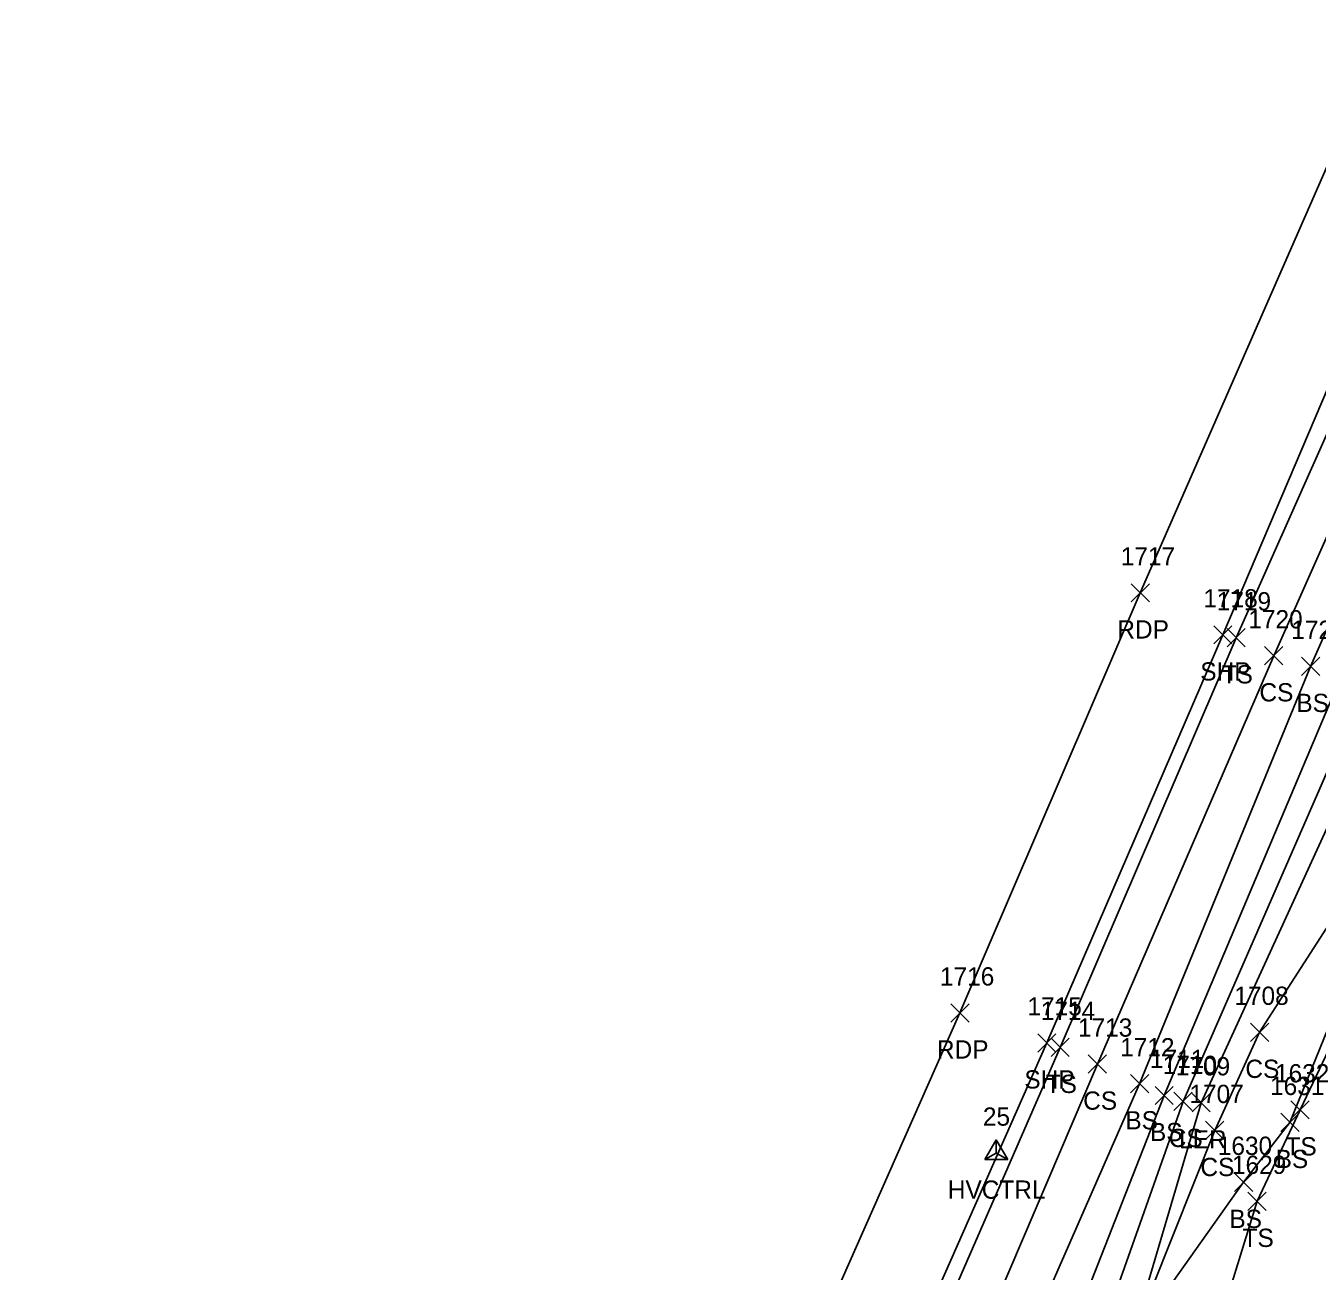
# Model space of a CAD drawing. Extents: x 1483143 to 1488182, y 802902 to 807581.
# Drawn here: x 1487613.3 to 1487754.7, y 806116.2 to 806252.6 of the extents above; entities that cross this region are included whole.
import ezdxf

# ---------------------------------------------------------------- set-up
doc = ezdxf.new("R2010")
doc.units = 0
for name, color, linetype in [('C_A', 7, 'Continuous'), ('C_I', 7, 'Continuous'), ('CPSM', 7, 'Continuous'), ('L_A', 7, 'Continuous'), ('L_I', 7, 'Continuous'), ('L_TIC', 7, 'Continuous'), ('LARO', 7, 'Continuous'), ('LELB', 7, 'Continuous'), ('P_A', 7, 'Continuous'), ('P_I', 7, 'Continuous'), ('P_TIC', 7, 'Continuous'), ('PET', 7, 'Continuous'), ('PSP', 7, 'Continuous')]:
    doc.layers.add(name, color=color, linetype=linetype)

msp = doc.modelspace()

# ---------------------------------------------------------------- linework, layer by layer
at = {"layer": 'CPSM'}
for p, q in [((1487718.34, 806128.4), (1487719.59, 806130.56)), ((1487720.84, 806128.4), (1487719.59, 806130.56)), ((1487719.59, 806129.12), (1487719.59, 806130.56)), ((1487718.34, 806128.4), (1487719.59, 806129.12)), ((1487718.34, 806128.4), (1487720.84, 806128.4)), ((1487719.59, 806129.12), (1487719.59, 806129.12)), ((1487719.59, 806129.12), (1487720.84, 806128.4))]:
    msp.add_line(p, q, dxfattribs=at)
at = {"layer": 'L_TIC'}
for points in [[(1487744.85, 806184.55), (1487746.85, 806186.55)], [(1487746.85, 806184.55), (1487744.85, 806186.55)], [(1487748.96, 806182.58), (1487750.96, 806184.58)], [(1487750.96, 806182.58), (1487748.96, 806184.58)], [(1487753, 806181.42), (1487755, 806183.42)], [(1487755, 806181.42), (1487753, 806183.42)], [(1487747.42, 806141.35), (1487749.42, 806143.35)], [(1487749.42, 806141.35), (1487747.42, 806143.35)], [(1487725.58, 806139.7), (1487727.58, 806141.7)], [(1487727.58, 806139.7), (1487725.58, 806141.7)], [(1487729.65, 806137.87), (1487731.65, 806139.87)], [(1487731.65, 806137.87), (1487729.65, 806139.87)], [(1487734.28, 806135.71), (1487736.28, 806137.71)], [(1487736.28, 806135.71), (1487734.28, 806137.71)], [(1487736.97, 806134.43), (1487738.97, 806136.43)], [(1487738.97, 806134.43), (1487736.97, 806136.43)], [(1487739.03, 806133.78), (1487741.03, 806135.78)], [(1487741.03, 806133.78), (1487739.03, 806135.78)], [(1487741.02, 806133.63), (1487743.02, 806135.63)], [(1487743.02, 806133.63), (1487741.02, 806135.63)], [(1487751.84, 806132.86), (1487753.84, 806134.86)], [(1487753.84, 806132.86), (1487751.84, 806134.86)], [(1487742.5, 806130.6), (1487744.5, 806132.6)], [(1487744.5, 806130.6), (1487742.5, 806132.6)], [(1487750.73, 806131.48), (1487752.73, 806133.48)], [(1487752.73, 806131.48), (1487750.73, 806133.48)], [(1487745.67, 806124.92), (1487747.67, 806126.92)], [(1487747.67, 806124.92), (1487745.67, 806126.92)], [(1487747.14, 806122.84), (1487749.14, 806124.84)], [(1487749.14, 806122.84), (1487747.14, 806124.84)]]:
    msp.add_lwpolyline(points, dxfattribs=at)
at = {"layer": 'LARO'}
msp.add_lwpolyline([(1487666.95, 805964.97), (1487680.31, 805984.75), (1487702.99, 806037.2), (1487715.7, 806058.03), (1487734.3, 806108.53), (1487742.02, 806134.63), (1487761.66, 806177.53), (1487786.65, 806227.9), (1487808.03, 806277.33), (1487813.76, 806294.17), (1487828.9, 806329), (1487831.91, 806346.68), (1487843.29, 806372.21), (1487845.69, 806380.48), (1487852.63, 806386.9), (1487863.18, 806416.3)], dxfattribs=at)
at = {"layer": 'LELB'}
for points in [[(1487406.66, 805485.41), (1487431.45, 805531.24), (1487454.84, 805575.74), (1487473.75, 805612.05), (1487489.43, 805642.37), (1487507.64, 805678.53), (1487524.82, 805711.39), (1487541.86, 805746.09), (1487557.67, 805776.44), (1487575.49, 805812.01), (1487597.52, 805857.93), (1487620.62, 805906.82), (1487641.85, 805951.94), (1487662.18, 805996.35), (1487684.09, 806043.93), (1487694.42, 806066.95), (1487726.58, 806140.7), (1487745.85, 806185.55), (1487769.04, 806237.65), (1487788.58, 806284.85), (1487808.3, 806333.26), (1487827.52, 806379.6), (1487850.09, 806437.73)], [(1487410.04, 805483.24), (1487436.07, 805529.53), (1487459.78, 805575.03), (1487477.42, 805609.67), (1487492.45, 805639.09), (1487509.86, 805677.27), (1487528.68, 805708.85), (1487545.3, 805744.17), (1487561.79, 805774.32), (1487579.7, 805810.21), (1487602.04, 805856.31), (1487624.97, 805905.57), (1487645.72, 805950.02), (1487667.21, 805993.1), (1487687.16, 806043.23), (1487699.2, 806065.16), (1487730.65, 806138.87), (1487749.96, 806183.58), (1487772.93, 806235.17), (1487792.36, 806283.08), (1487812.9, 806331.5), (1487831.61, 806378.23), (1487855.61, 806436.65)], [(1487413.83, 805481.53), (1487440.22, 805526.89), (1487464.36, 805572.85), (1487481.71, 805606.55), (1487496.63, 805636.25), (1487514.9, 805673.97), (1487535.8, 805705.94), (1487549.07, 805741.59), (1487566.17, 805772.22), (1487583.99, 805807.69), (1487605.26, 805855.28), (1487629.33, 805903.01), (1487650.26, 805948.76), (1487670.48, 805991.25), (1487690.28, 806041.74), (1487702.22, 806061.37), (1487704.47, 806066.39), (1487735.28, 806136.71), (1487754, 806182.42), (1487776.55, 806233.47), (1487796.75, 806281.41), (1487816.88, 806330.25), (1487835.19, 806376.59), (1487859.78, 806434.97)], [(1487417, 805480.8), (1487442.28, 805525.8), (1487466.47, 805571.82), (1487483.84, 805604.86), (1487498.25, 805635.76), (1487518.24, 805671.86), (1487538.47, 805704.77), (1487552.2, 805739.67), (1487568.17, 805771.84), (1487585.97, 805806.76), (1487609.39, 805853.47), (1487632.34, 805900.81), (1487653.02, 805947.32), (1487672.59, 805990.01), (1487694.92, 806039.27), (1487707.45, 806059.25), (1487710.05, 806064.3), (1487737.97, 806135.43), (1487757.4, 806181.42), (1487778.76, 806231.94), (1487799.97, 806279.97), (1487818.92, 806329.91), (1487837.5, 806376), (1487863.45, 806433.38)], [(1487539.8, 805706.7), (1487554.99, 805738.51), (1487564.78, 805761.24), (1487572.42, 805770.06), (1487590.42, 805804.18), (1487613.31, 805851.36), (1487639.64, 805896.3), (1487657.07, 805945.9), (1487666.95, 805964.97), (1487675.89, 805987.99), (1487698.82, 806037.9), (1487713.56, 806059.8), (1487740.03, 806134.78), (1487759.8, 806179.98), (1487782.43, 806230.23), (1487804.48, 806278.55), (1487821.45, 806329.34), (1487839.66, 806374.66), (1487865.87, 806433.14)], [(1487734.3, 806108.53), (1487743.5, 806131.6), (1487748.42, 806142.35), (1487768.3, 806173.23), (1487776.95, 806194.07), (1487797.73, 806226.32)], [(1487709.5, 806045.03), (1487721.98, 806050.95), (1487727.79, 806058.8), (1487736.06, 806080.69), (1487739.04, 806093.16), (1487735.83, 806103.47), (1487734.3, 806108.53), (1487746.67, 806125.92), (1487751.73, 806132.48), (1487759.26, 806150.98), (1487768.04, 806168.06), (1487779.72, 806187.39)], [(1487709.97, 806043.56), (1487721.56, 806049.74), (1487727.77, 806058.21), (1487737.69, 806079.55), (1487741.2, 806090.9), (1487742.36, 806105.05), (1487748.14, 806123.84), (1487752.84, 806133.86), (1487761.63, 806152.29), (1487779.72, 806187.39)]]:
    msp.add_lwpolyline(points, dxfattribs=at)
at = {"layer": 'P_TIC'}
for points in [[(1487734.35, 806189.47), (1487736.35, 806191.47)], [(1487736.35, 806189.47), (1487734.35, 806191.47)], [(1487743.39, 806184.87), (1487745.39, 806186.87)], [(1487745.39, 806184.87), (1487743.39, 806186.87)], [(1487714.61, 806143.47), (1487716.61, 806145.47)], [(1487716.61, 806143.47), (1487714.61, 806145.47)], [(1487724.12, 806140.19), (1487726.12, 806142.19)], [(1487726.12, 806140.19), (1487724.12, 806142.19)]]:
    msp.add_lwpolyline(points, dxfattribs=at)
at = {"layer": 'PET'}
msp.add_lwpolyline([(1487396.33, 805490.41), (1487421.9, 805537.94), (1487444.13, 805580.16), (1487464.29, 805618.83), (1487479.8, 805648.39), (1487498.08, 805684.27), (1487514.57, 805717.15), (1487530.55, 805749.06), (1487547.16, 805782.47), (1487564.33, 805817.54), (1487585.71, 805863.32), (1487608.89, 805911.38), (1487630.35, 805956.68), (1487651.22, 806001.25), (1487672.63, 806048.33), (1487683.65, 806072.29), (1487715.61, 806144.47), (1487735.35, 806190.47), (1487757.48, 806241.03), (1487777.65, 806289.15), (1487798.25, 806337.46), (1487817.05, 806384.04), (1487839.67, 806441.4)], dxfattribs=at)
at = {"layer": 'PSP'}
msp.add_lwpolyline([(1487405.03, 805486.21), (1487429.8, 805532.42), (1487452.92, 805576.31), (1487472.37, 805613.24), (1487487.86, 805643.29), (1487506.35, 805679.4), (1487523.34, 805712.45), (1487540.38, 805746.64), (1487556.03, 805777.85), (1487573.44, 805813.27), (1487595.34, 805859.04), (1487618.37, 805906.67), (1487640.09, 805952.42), (1487660.18, 805997.21), (1487682.38, 806044.71), (1487693.04, 806068.56), (1487725.12, 806141.19), (1487744.39, 806185.87), (1487766.81, 806238.55), (1487786.8, 806285.64), (1487806.77, 806333.93), (1487825.55, 806380.21), (1487847.81, 806437.56)], dxfattribs=at)

# ---------------------------------------------------------------- texts
at = {"layer": 'C_A'}
msp.add_text('HVCTRL', height=2, dxfattribs=at).set_placement((1487714.28, 806124.12))
at = {"layer": 'C_I'}
msp.add_text('25', height=2, dxfattribs=at).set_placement((1487718.12, 806132.12))
at = {"layer": 'L_A'}
for s, p in [('TS', (1487744.26, 806180.55)), ('CS', (1487748.4, 806178.58)), ('BS', (1487752.44, 806177.42)), ('CS', (1487746.86, 806137.35)), ('TS', (1487724.99, 806135.7)), ('CS', (1487729.1, 806133.87)), ('BS', (1487733.72, 806131.71)), ('BS', (1487736.41, 806130.43)), ('CS', (1487738.47, 806129.78)), ('LER', (1487739.6, 806129.63)), ('TS', (1487751.25, 806128.86)), ('BS', (1487750.17, 806127.48)), ('CS', (1487741.94, 806126.6)), ('BS', (1487745.11, 806120.92)), ('TS', (1487746.55, 806118.84))]:
    msp.add_text(s, height=2, dxfattribs=at).set_placement(p)
at = {"layer": 'L_I'}
for s, p in [('1719', (1487743.72, 806188.55)), ('1720', (1487747.18, 806186.58)), ('1721', (1487751.88, 806185.42)), ('1708', (1487745.65, 806145.35)), ('1714', (1487724.46, 806143.7)), ('1713', (1487728.53, 806141.87)), ('1712', (1487733.15, 806139.71)), ('1711', (1487736.41, 806138.43)), ('1710', (1487737.81, 806137.78)), ('1709', (1487739.24, 806137.63)), ('1632', (1487750.1, 806136.86)), ('1707', (1487740.73, 806134.6)), ('1631', (1487749.56, 806135.48)), ('1630', (1487743.84, 806128.92)), ('1629', (1487745.39, 806126.84))]:
    msp.add_text(s, height=2, dxfattribs=at).set_placement(p)
at = {"layer": 'P_A'}
for s, p in [('RDP', (1487732.84, 806185.47)), ('SHP', (1487741.92, 806180.87)), ('RDP', (1487713.09, 806139.47)), ('SHP', (1487722.66, 806136.19))]:
    msp.add_text(s, height=2, dxfattribs=at).set_placement(p)
at = {"layer": 'P_I'}
for s, p in [('1717', (1487733.22, 806193.47)), ('1718', (1487742.26, 806188.87)), ('1716', (1487713.42, 806147.47)), ('1715', (1487723, 806144.19))]:
    msp.add_text(s, height=2, dxfattribs=at).set_placement(p)

doc.saveas('drawing.dxf')
